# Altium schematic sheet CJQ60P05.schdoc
size 127 x 101 mm
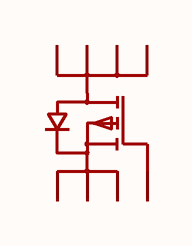
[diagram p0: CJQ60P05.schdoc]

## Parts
Q?  cjq60p05  [SOP-8_L4.9-W3.9-P1.27-LS6.0-BL-1]  (value not drawn)

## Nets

Not connected (* = marked no-connect by the designer): Q? 1(S) 2(S) 3(S) 4(G) 5(D) 6(D) 7(D) 8(D)

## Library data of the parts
Q? = cjq60p05: 数量:1个P沟道;漏源电压(Vdss):60V;连续漏极电流(Id):5A;导通电阻(RDS(on)):58mΩ@10V;耗散功率(Pd):-;阈值电压(Vgs(th)):3.5V;; Manufacturer: CJ(江苏长电/长晶); AddInBom: yes; ModelId: 75c24a7891ee4dd6bdac16a7163ff87e; ModelTransform: 192.913,236.22,0,0,0,0,0,0,0; Number: 1个P沟道; Drain to Source Voltage: 60V; Current - Continuous Drain(Id): 5A; Gate Threshold Voltage (Vgs(th)): 3.5V; Gate Charge(Qg): 26nC@10V; Input Capacitance(Ciss): 1.45nF; Reverse Transfer Capacitance (Crss@Vds): 110pF; Type: P沟道; Output Capacitance(Coss): 145pF; Vgs: ±20V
